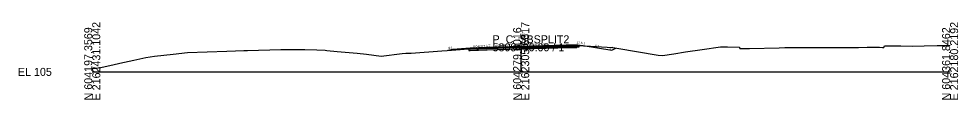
# Model space of a CAD drawing. Extents: x -26 to 1303, y -10 to 12033.
# Drawn here: x 974.3 to 1302.8, y 2490.3 to 2517.3 of the extents above; entities that cross this region are included whole.
import ezdxf

# ---------------------------------------------------------------- set-up
doc = ezdxf.new("R2010")
doc.units = 0
for name, color, linetype in [('RD_GPK_XS_Cell', 7, 'Continuous'), ('RD_XS_Base', 7, 'Continuous'), ('RD_XS_ExGround', 7, 'Continuous'), ('RD_XS_ExPaveRet', 7, 'Continuous'), ('RD_XS_Greenside', 7, 'Continuous'), ('RD_XS_Pave', 7, 'Continuous'), ('RD_XS_PaveOvlay_CP', 7, 'Continuous'), ('RD_XS_TieSlope', 7, 'Continuous'), ('RD_XS_TX_Elev_EX', 7, 'Continuous'), ('RD_XS_TX_Elev_PR', 7, 'Continuous'), ('RD_XS_TX_ShdSlope', 7, 'Continuous'), ('RD_XS_TX_Slope', 7, 'Continuous')]:
    doc.layers.add(name, color=color, linetype=linetype)

msp = doc.modelspace()

# ---------------------------------------------------------------- linework, layer by layer
at = {"layer": 'RD_GPK_XS_Cell'}
for p, q in [((1150, 2500), (1150, 2510)), ((1000, 2500), (1150, 2500)), ((1150, 2500), (1300, 2500))]:
    msp.add_line(p, q, dxfattribs=at)
at = {"layer": 'RD_XS_Base'}
for p, q in [((1132.15, 2507.99), (1131.65, 2507.97)), ((1131.65, 2507.97), (1131.65, 2507.97)), ((1131.65, 2507.97), (1131.65, 2507.47)), ((1131.65, 2507.47), (1132.15, 2507.49)), ((1138, 2508.22), (1132.15, 2507.99)), ((1132.15, 2507.99), (1132.15, 2507.99)), ((1132.15, 2507.49), (1138, 2507.72)), ((1132.15, 2507.49), (1132.15, 2507.49)), ((1150, 2508.56), (1138, 2508.22)), ((1138, 2508.22), (1138, 2508.22)), ((1138, 2507.72), (1150, 2508.06)), ((1138, 2507.72), (1138, 2507.72)), ((1150, 2508.56), (1169.66, 2509.11)), ((1150, 2508.06), (1150, 2508.72)), ((1150, 2508.72), (1150, 2508.72)), ((1150, 2508.72), (1150, 2508.72)), ((1150, 2508.72), (1150, 2508.56)), ((1170.16, 2508.62), (1150, 2508.06)), ((1150, 2508.56), (1150, 2508.56)), ((1150, 2508.06), (1150, 2508.56)), ((1150, 2508.56), (1150, 2508.56)), ((1150, 2508.56), (1150, 2508.56)), ((1150, 2508.06), (1150, 2508.06)), ((1162, 2508.89), (1162, 2508.89)), ((1162, 2508.89), (1162, 2508.89)), ((1162, 2508.39), (1162, 2508.39)), ((1162, 2508.39), (1162, 2508.39)), ((1169.66, 2509.11), (1169.66, 2509.11)), ((1170.16, 2509.12), (1170.16, 2508.62)), ((1170.16, 2509.09), (1170.16, 2509.09))]:
    msp.add_line(p, q, dxfattribs=at)
at = {"layer": 'RD_XS_ExGround'}
msp.add_lwpolyline([(1000, 2501.1), (1000.32, 2501.14), (1003.05, 2501.47), (1005.55, 2502.08), (1007.16, 2502.51), (1009.61, 2503.04), (1014.57, 2504.12), (1018.77, 2504.97), (1021.74, 2505.52), (1028.26, 2506.2), (1033.32, 2506.73), (1047.1, 2507.3), (1050.05, 2507.41), (1052.98, 2507.44), (1053.28, 2507.45), (1053.54, 2507.46), (1054.25, 2507.5), (1065.96, 2507.77), (1067.64, 2507.8), (1068.84, 2507.84), (1070.48, 2507.82), (1074.32, 2507.79), (1078.55, 2507.76), (1081.44, 2507.56), (1082.09, 2507.51), (1085.62, 2507.16), (1092.63, 2506.5), (1095.89, 2506.15), (1101.09, 2505.54), (1108.42, 2506.38), (1109.69, 2506.51), (1110.03, 2506.51), (1111.5, 2506.5), (1122.28, 2507.36), (1124.07, 2507.5), (1125.66, 2507.63), (1134.61, 2508.3), (1141.7, 2508.53), (1149.81, 2508.8), (1150.03, 2508.8), (1150.04, 2508.81), (1150.04, 2508.81), (1150.06, 2508.81), (1150.51, 2508.82), (1162.8, 2509.12), (1169.42, 2509.28), (1171.79, 2509.12), (1172.3, 2509.09), (1182.03, 2508.51), (1183.42, 2508.26), (1197.94, 2505.88), (1199.37, 2505.68), (1203.35, 2506.32), (1207.5, 2506.98), (1213.25, 2507.83), (1219.68, 2508.74), (1222.21, 2508.72), (1226.32, 2508.62), (1226.34, 2508.54), (1226.47, 2508.12), (1226.69, 2508.13), (1227.88, 2508.17), (1229.83, 2508.21), (1240.18, 2508.45), (1242.23, 2508.48), (1245.65, 2508.5), (1246.42, 2508.5), (1246.74, 2508.5), (1252.27, 2508.5), (1257.15, 2508.53), (1260.69, 2508.55), (1267.97, 2508.58), (1271.02, 2508.59), (1272.32, 2508.62), (1275.33, 2508.61), (1276.31, 2508.58), (1276.86, 2508.56), (1276.97, 2508.86), (1277.04, 2509.06), (1277.27, 2509.06), (1277.44, 2509.06), (1282.72, 2509.07), (1286.77, 2509.03), (1290.95, 2509.14), (1295.43, 2509.25), (1298.04, 2509.27), (1300, 2509.31)], dxfattribs=at)
at = {"layer": 'RD_XS_ExPaveRet'}
for points in [[(1162.8, 2509.12), (1150.51, 2508.82), (1150.51, 2508.82), (1150.06, 2508.81), (1150.04, 2508.81), (1150.04, 2508.81), (1150.03, 2508.8), (1149.81, 2508.8), (1149.81, 2508.8), (1141.7, 2508.53), (1141.7, 2508.53), (1134.61, 2508.3), (1134.61, 2508.3), (1134.61, 2507.55), (1141.7, 2507.78), (1141.7, 2507.78), (1149.81, 2508.05), (1149.81, 2508.05), (1150.03, 2508.05), (1150.04, 2508.06), (1150.04, 2508.06), (1150.06, 2508.06), (1150.51, 2508.07), (1150.51, 2508.07), (1162.8, 2508.37), (1162.8, 2508.37), (1169.42, 2508.53), (1169.42, 2509.28), (1169.42, 2509.28), (1162.8, 2509.12), (1162.8, 2509.12)], [(1162.8, 2509.12), (1150.51, 2508.82), (1150.06, 2508.81), (1150.04, 2508.81), (1150.04, 2508.81), (1150.03, 2508.8), (1149.81, 2508.8), (1141.7, 2508.53), (1134.61, 2508.3), (1134.61, 2507.55), (1141.7, 2507.78), (1149.81, 2508.05), (1150.03, 2508.05), (1150.04, 2508.06), (1150.04, 2508.06), (1150.06, 2508.06), (1150.51, 2508.07), (1162.8, 2508.37), (1169.42, 2508.53), (1169.42, 2509.28), (1162.8, 2509.12)]]:
    msp.add_lwpolyline(points, dxfattribs=at)
at = {"layer": 'RD_XS_Greenside'}
for p, q in [((1126.15, 2507.83), (1124.36, 2507.53)), ((1171.66, 2509.27), (1181.66, 2507.6)), ((1181.66, 2507.6), (1183.1, 2508.32))]:
    msp.add_line(p, q, dxfattribs=at)
at = {"layer": 'RD_XS_Pave'}
for p, q in [((1138, 2508.54), (1132.15, 2508.31)), ((1132.15, 2508.15), (1138, 2508.38)), ((1138, 2508.38), (1132.15, 2508.15)), ((1132.15, 2508.31), (1132.15, 2508.31)), ((1132.15, 2508.31), (1132.15, 2508.15)), ((1132.15, 2507.99), (1138, 2508.22)), ((1132.15, 2508.15), (1132.15, 2508.15)), ((1132.15, 2508.15), (1132.15, 2507.99)), ((1150, 2508.88), (1138, 2508.54)), ((1138, 2508.38), (1150, 2508.72)), ((1150, 2508.72), (1138, 2508.38)), ((1138, 2508.22), (1150, 2508.56)), ((1138, 2508.54), (1138, 2508.54)), ((1138, 2508.38), (1138, 2508.38)), ((1138, 2508.38), (1138, 2508.38)), ((1138, 2508.22), (1138, 2508.22)), ((1169.66, 2509.43), (1150, 2508.88)), ((1169.66, 2509.27), (1150, 2508.72)), ((1150, 2508.72), (1169.66, 2509.27)), ((1150, 2508.56), (1170.16, 2509.12)), ((1150, 2508.88), (1150, 2508.88)), ((1150, 2508.72), (1150, 2508.72)), ((1150, 2508.72), (1150, 2508.72)), ((1150, 2508.72), (1150, 2508.56)), ((1150, 2508.72), (1150, 2508.72)), ((1150, 2508.56), (1150, 2508.72)), ((1150, 2508.72), (1150, 2508.72)), ((1150, 2508.72), (1150, 2508.72)), ((1150, 2508.56), (1150, 2508.56)), ((1150, 2508.56), (1150, 2508.56)), ((1162, 2509.21), (1162, 2509.21)), ((1162, 2509.21), (1162, 2509.21)), ((1162, 2509.05), (1162, 2509.05)), ((1162, 2509.05), (1162, 2509.05)), ((1162, 2509.05), (1162, 2509.05)), ((1162, 2509.05), (1162, 2509.05)), ((1162, 2508.89), (1162, 2508.89)), ((1162, 2508.89), (1162, 2508.89)), ((1169.66, 2509.27), (1169.66, 2509.43)), ((1169.66, 2509.43), (1169.66, 2509.43)), ((1169.66, 2509.11), (1169.66, 2509.27)), ((1169.66, 2509.27), (1169.66, 2509.27))]:
    msp.add_line(p, q, dxfattribs=at)
at = {"layer": 'RD_XS_PaveOvlay_CP'}
for p, q in [((1138, 2508.54), (1132.15, 2508.31)), ((1150, 2508.88), (1138, 2508.54)), ((1138, 2508.54), (1138, 2508.54)), ((1169.66, 2509.43), (1150, 2508.88)), ((1150, 2508.88), (1150, 2508.88)), ((1162, 2509.21), (1162, 2509.21)), ((1162, 2509.21), (1162, 2509.21))]:
    msp.add_line(p, q, dxfattribs=at)
at = {"layer": 'RD_XS_TieSlope'}
for p, q in [((1132.15, 2508.31), (1126.15, 2507.83)), ((1169.66, 2509.43), (1171.66, 2509.27))]:
    msp.add_line(p, q, dxfattribs=at)

# ---------------------------------------------------------------- texts
at = {"layer": 'RD_GPK_XS_Cell'}
for s, p in [('E 2162431.1042', (1002.8, 2490)), ('E 2162305.6617', (1152.8, 2490)), ('E 2162180.2192', (1302.8, 2490)), ('N 604197.3569', (1000, 2490)), ('N 604279.6016', (1150, 2490)), ('N 604361.8462', (1300, 2490))]:
    msp.add_text(s, height=2.8, rotation=90, dxfattribs=at).set_placement(p)
for s, p in [('5309+00.00 / 1', (1140, 2507.2)), ('P_C_SBSPLIT2', (1140, 2510)), ('EL 105', (974, 2498.6))]:
    msp.add_text(s, height=2.8, dxfattribs=at).set_placement(p)
at = {"layer": 'RD_XS_TX_Elev_EX'}
msp.add_text('113.80', height=0.6, rotation=90, dxfattribs=at).set_placement((1149.63, 2509.75))
at = {"layer": 'RD_XS_TX_Elev_PR'}
msp.add_text('113.88', height=1, rotation=90, dxfattribs=at).set_placement((1151.3, 2509.2))
at = {"layer": 'RD_XS_TX_ShdSlope'}
msp.add_text('12.5:1', height=0.75, rotation=355.4261, dxfattribs=at).set_placement((1169.38, 2509.89))
at = {"layer": 'RD_XS_TX_Slope'}
for s, rotation, p in [('6:1', 9.4623, (1124.64, 2507.96)), ('0.040 FT./FT.', 2.2906, (1133.23, 2508.5)), ('0.030 FT./FT.', 1.7184, (1140.41, 2508.79)), ('0.030 FT./FT.', 1.7184, (1153.16, 2509.06)), ('6:1', 350.5358, (1175.79, 2508.87)), ('2:1', 26.5651, (1181.07, 2507.64))]:
    msp.add_text(s, height=0.75, rotation=rotation, dxfattribs=at).set_placement(p)

doc.saveas('drawing.dxf')
